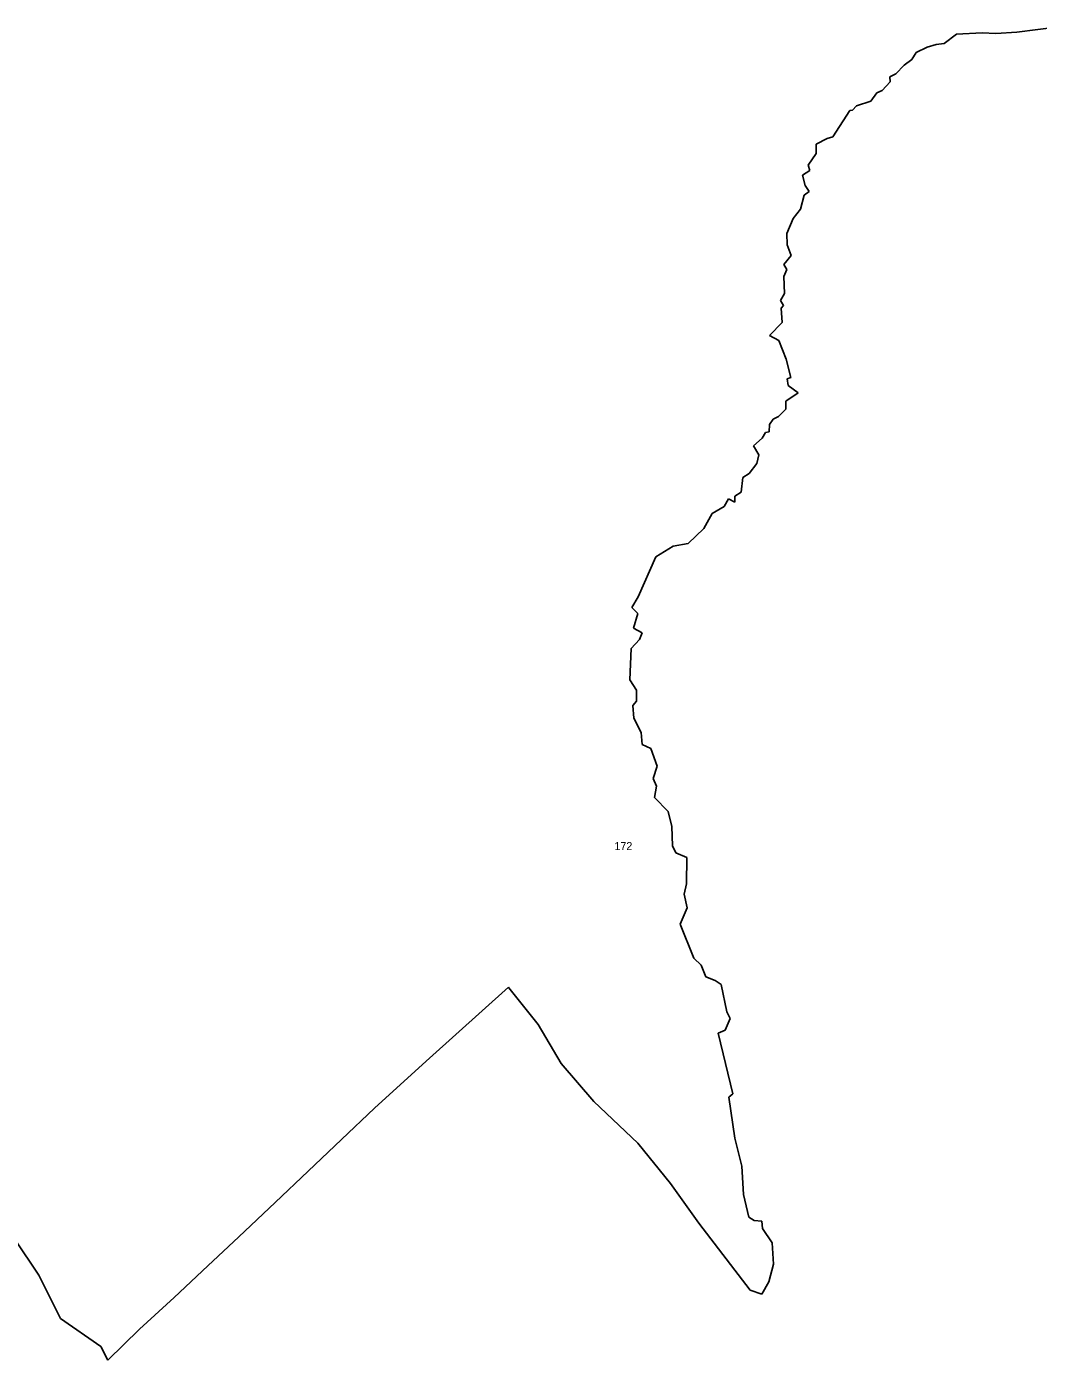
# Model space of a CAD drawing. Extents: x -787692 to -782531, y -972586 to -966265.
# Drawn here: x -785099 to -783835, y -972586 to -970919 of the extents above; entities that cross this region are included whole.
import ezdxf

# ---------------------------------------------------------------- set-up
doc = ezdxf.new("R2010")
doc.units = 0
doc.layers.add('Vrstva 13', color=7, linetype='Continuous')
doc.layers.add('Vrstva 24', color=7, linetype='Continuous')

msp = doc.modelspace()

# ---------------------------------------------------------------- linework, layer by layer
at = {"layer": 'Vrstva 13'}
for p, q in [((-783861.89, -970925.86), (-783809.33, -970919.07)), ((-783952.54, -970940.18), (-783937.34, -970928.36)), ((-783937.34, -970928.36), (-783905.08, -970926.59)), ((-783905.08, -970926.59), (-783888.09, -970927.72)), ((-783888.09, -970927.72), (-783861.89, -970925.86)), ((-783993.14, -970960.16), (-783987.64, -970951.5)), ((-783987.64, -970951.5), (-783973.81, -970944.71)), ((-783973.81, -970944.71), (-783962.65, -970941.39)), ((-783962.65, -970941.39), (-783952.54, -970940.18)), ((-784012.87, -970978.2), (-784002.6, -970967.2)), ((-784002.6, -970967.2), (-783993.14, -970960.16)), ((-784020.55, -970981.6), (-784012.87, -970978.2)), ((-784019.91, -970987.83), (-784020.55, -970981.6)), ((-784044.01, -971012.26), (-784036.73, -971001.82)), ((-784036.73, -971001.82), (-784030.02, -970998.91)), ((-784030.02, -970998.91), (-784019.91, -970987.83)), ((-784066.89, -971023.59), (-784061.96, -971017.85)), ((-784061.96, -971017.85), (-784044.01, -971012.26)), ((-784091.56, -971056.93), (-784070.37, -971023.83)), ((-784070.37, -971023.83), (-784066.89, -971023.59)), ((-784112.59, -971065.74), (-784098.68, -971058.95)), ((-784112.51, -971077.39), (-784112.59, -971065.74)), ((-784098.68, -971058.95), (-784091.56, -971056.93)), ((-784122.3, -971092.24), (-784112.51, -971077.39)), ((-784129.58, -971104.7), (-784120.2, -971098.88)), ((-784120.2, -971098.88), (-784122.3, -971092.24)), ((-784126.34, -971117.49), (-784129.58, -971104.7)), ((-784121.17, -971124.93), (-784126.34, -971117.49)), ((-784132.13, -971147.2), (-784127.47, -971129.62)), ((-784127.47, -971129.62), (-784121.17, -971124.93)), ((-784141.02, -971158.69), (-784132.13, -971147.2)), ((-784149.15, -971177.74), (-784141.02, -971158.69)), ((-784148.82, -971191.9), (-784149.15, -971177.74)), ((-784143.77, -971204.97), (-784148.82, -971191.9)), ((-784153.02, -971216.46), (-784143.77, -971204.97)), ((-784149.02, -971222.45), (-784153.02, -971216.46)), ((-784152.7, -971231.29), (-784149.02, -971222.45)), ((-784151.89, -971252.73), (-784152.7, -971231.29)), ((-784156.98, -971261.39), (-784151.89, -971252.73)), ((-784153.35, -971267.7), (-784156.98, -971261.39)), ((-784156.09, -971270.98), (-784153.35, -971267.7)), ((-784154.8, -971288.61), (-784156.09, -971270.98)), ((-784170.97, -971304.96), (-784154.8, -971288.61)), ((-784159.16, -971311.43), (-784170.97, -971304.96)), ((-784150.15, -971334.67), (-784159.16, -971311.43)), ((-784144.2, -971357.44), (-784150.15, -971334.67)), ((-784148.73, -971359.34), (-784144.2, -971357.44)), ((-784147.4, -971367.59), (-784148.73, -971359.34)), ((-784135.02, -971376.52), (-784147.4, -971367.59)), ((-784150.47, -971387.04), (-784135.02, -971376.52)), ((-784159.69, -971406.5), (-784150.39, -971397.12)), ((-784150.39, -971397.12), (-784150.47, -971387.04)), ((-784171.37, -971425.37), (-784170.73, -971416.31)), ((-784170.73, -971416.31), (-784166.08, -971409.57)), ((-784166.08, -971409.57), (-784159.69, -971406.5)), ((-784190.94, -971442.92), (-784179.86, -971433.3)), ((-784179.86, -971433.3), (-784175.98, -971426.1)), ((-784175.98, -971426.1), (-784171.37, -971425.37)), ((-784184.15, -971454.17), (-784190.94, -971442.92)), ((-784196.2, -971477.63), (-784186.42, -971464.85)), ((-784186.42, -971464.85), (-784184.15, -971454.17)), ((-784206.15, -971500.89), (-784204.29, -971482.65)), ((-784204.29, -971482.65), (-784196.2, -971477.63)), ((-784214.24, -971505.91), (-784206.15, -971500.89)), ((-784242.46, -971527.55), (-784227.5, -971518.69)), ((-784227.5, -971518.69), (-784222, -971509.14)), ((-784222, -971509.14), (-784214.07, -971513.19)), ((-784214.07, -971513.19), (-784214.24, -971505.91)), ((-784252.97, -971546.48), (-784242.46, -971527.55)), ((-784272.62, -971564.89), (-784252.97, -971546.48)), ((-784312.73, -971581.87), (-784291.22, -971568.45)), ((-784291.22, -971568.45), (-784272.62, -971564.89)), ((-784334.89, -971631.87), (-784312.73, -971581.87)), ((-784342.65, -971645.14), (-784334.89, -971631.87)), ((-784335.14, -971652.39), (-784342.65, -971645.14)), ((-784340.54, -971671.06), (-784335.14, -971652.39)), ((-784343.66, -971696.11), (-784333.07, -971685.23)), ((-784330.07, -971676.79), (-784340.54, -971671.06)), ((-784333.07, -971685.23), (-784330.07, -971676.79)), ((-784345.45, -971735.58), (-784343.66, -971696.11)), ((-784336.92, -971748.35), (-784345.45, -971735.58)), ((-784336.81, -971762.08), (-784336.92, -971748.35)), ((-784341.57, -971767.56), (-784336.81, -971762.08)), ((-784340.45, -971783.34), (-784341.57, -971767.56)), ((-784331.28, -971801.16), (-784340.45, -971783.34)), ((-784330.06, -971816.47), (-784331.28, -971801.16)), ((-784319.18, -971821.38), (-784330.06, -971816.47)), ((-784311.27, -971843.35), (-784319.18, -971821.38)), ((-784316.02, -971858.91), (-784311.27, -971843.35)), ((-784312.08, -971868.41), (-784316.02, -971858.91)), ((-784314.44, -971882.34), (-784312.08, -971868.41)), ((-784297.55, -971899.8), (-784314.44, -971882.34)), ((-784292.89, -971918.72), (-784297.55, -971899.8)), ((-784292.19, -971942.76), (-784292.89, -971918.72)), ((-784287.93, -971951.85), (-784292.19, -971942.76)), ((-784274.05, -971957.66), (-784287.93, -971951.85)), ((-784274.46, -971990.34), (-784274.05, -971957.66)), ((-784277.38, -972003.3), (-784274.46, -971990.34)), ((-784273.73, -972020.31), (-784277.38, -972003.3)), ((-784282.54, -972040.89), (-784273.73, -972020.31)), ((-784265.21, -972083.33), (-784282.54, -972040.89)), ((-784255.99, -972092.22), (-784265.21, -972083.33)), ((-784250.15, -972106.52), (-784255.99, -972092.22)), ((-784238.62, -972111.06), (-784250.15, -972106.52)), ((-784231.32, -972116.1), (-784238.62, -972111.06)), ((-784224.06, -972150.24), (-784231.32, -972116.1)), ((-784496.86, -972119.76), (-784595.63, -972208.5)), ((-784496.86, -972119.76), (-784496.56, -972120.25)), ((-784496.56, -972120.25), (-784460.03, -972166.38)), ((-784219.95, -972158.65), (-784224.06, -972150.24)), ((-784460.03, -972166.38), (-784431.14, -972215.02)), ((-784226.12, -972173.27), (-784219.95, -972158.65)), ((-784235.13, -972177), (-784226.12, -972173.27)), ((-784216.62, -972252.94), (-784235.13, -972177)), ((-784595.63, -972208.5), (-784622.66, -972232.94)), ((-784431.14, -972215.02), (-784390.23, -972262.28)), ((-784622.66, -972232.94), (-784664.54, -972270.94)), ((-784390.23, -972262.28), (-784335.37, -972314.66)), ((-784221.49, -972257), (-784216.62, -972252.94)), ((-784214.27, -972308.16), (-784221.49, -972257)), ((-784664.54, -972270.94), (-784705.44, -972309.91)), ((-784705.44, -972309.91), (-784747.16, -972349.37)), ((-784335.37, -972314.66), (-784294.46, -972364.93)), ((-784205.21, -972343.2), (-784214.27, -972308.16)), ((-784747.16, -972349.37), (-784788.3, -972388.59)), ((-784203.1, -972378.77), (-784205.21, -972343.2)), ((-784294.46, -972364.93), (-784258.9, -972414.55)), ((-784196.41, -972407.23), (-784203.1, -972378.77)), ((-784788.3, -972388.59), (-784833.74, -972431.46)), ((-784258.9, -972414.55), (-784194.85, -972498.1)), ((-784190.12, -972411.01), (-784196.41, -972407.23)), ((-784180.58, -972412.14), (-784190.12, -972411.01)), ((-784179.4, -972421.03), (-784180.58, -972412.14)), ((-785083.7, -972479.66), (-785114.14, -972434.15)), ((-784833.74, -972431.46), (-784872.78, -972467.99)), ((-784167.27, -972439.06), (-784179.4, -972421.03)), ((-784165.65, -972465.94), (-784167.27, -972439.06)), ((-784872.78, -972467.99), (-784914.81, -972507.46)), ((-784171.82, -972488.03), (-784165.65, -972465.94)), ((-785056.72, -972533.58), (-785083.7, -972479.66)), ((-784194.85, -972498.1), (-784180.41, -972503.22)), ((-784180.41, -972503.22), (-784171.82, -972488.03)), ((-784914.81, -972507.46), (-784957.75, -972547.01)), ((-785006.31, -972568.82), (-785056.72, -972533.58)), ((-784957.75, -972547.01), (-784997.71, -972585.97)), ((-784997.71, -972585.97), (-785006.31, -972568.82))]:
    msp.add_line(p, q, dxfattribs=at)

# ---------------------------------------------------------------- texts
at = {"layer": 'Vrstva 24'}
msp.add_text('172', height=10, dxfattribs=at).set_placement((-784364.54, -971948.17))

doc.saveas('drawing.dxf')
